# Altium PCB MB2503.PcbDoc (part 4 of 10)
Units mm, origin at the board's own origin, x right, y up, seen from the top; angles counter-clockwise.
Board outline 127 x 97 mm, 6 copper layers (Top Layer, Signal Layer 1, Signal Layer 2, Signal Layer 3, Signal Layer 4, Bottom Layer), stack 1.557 mm thick; 572 components, 468 nets, 2377 pads, 1704 vias.
Unrouted connection lines stored in the file: 3.
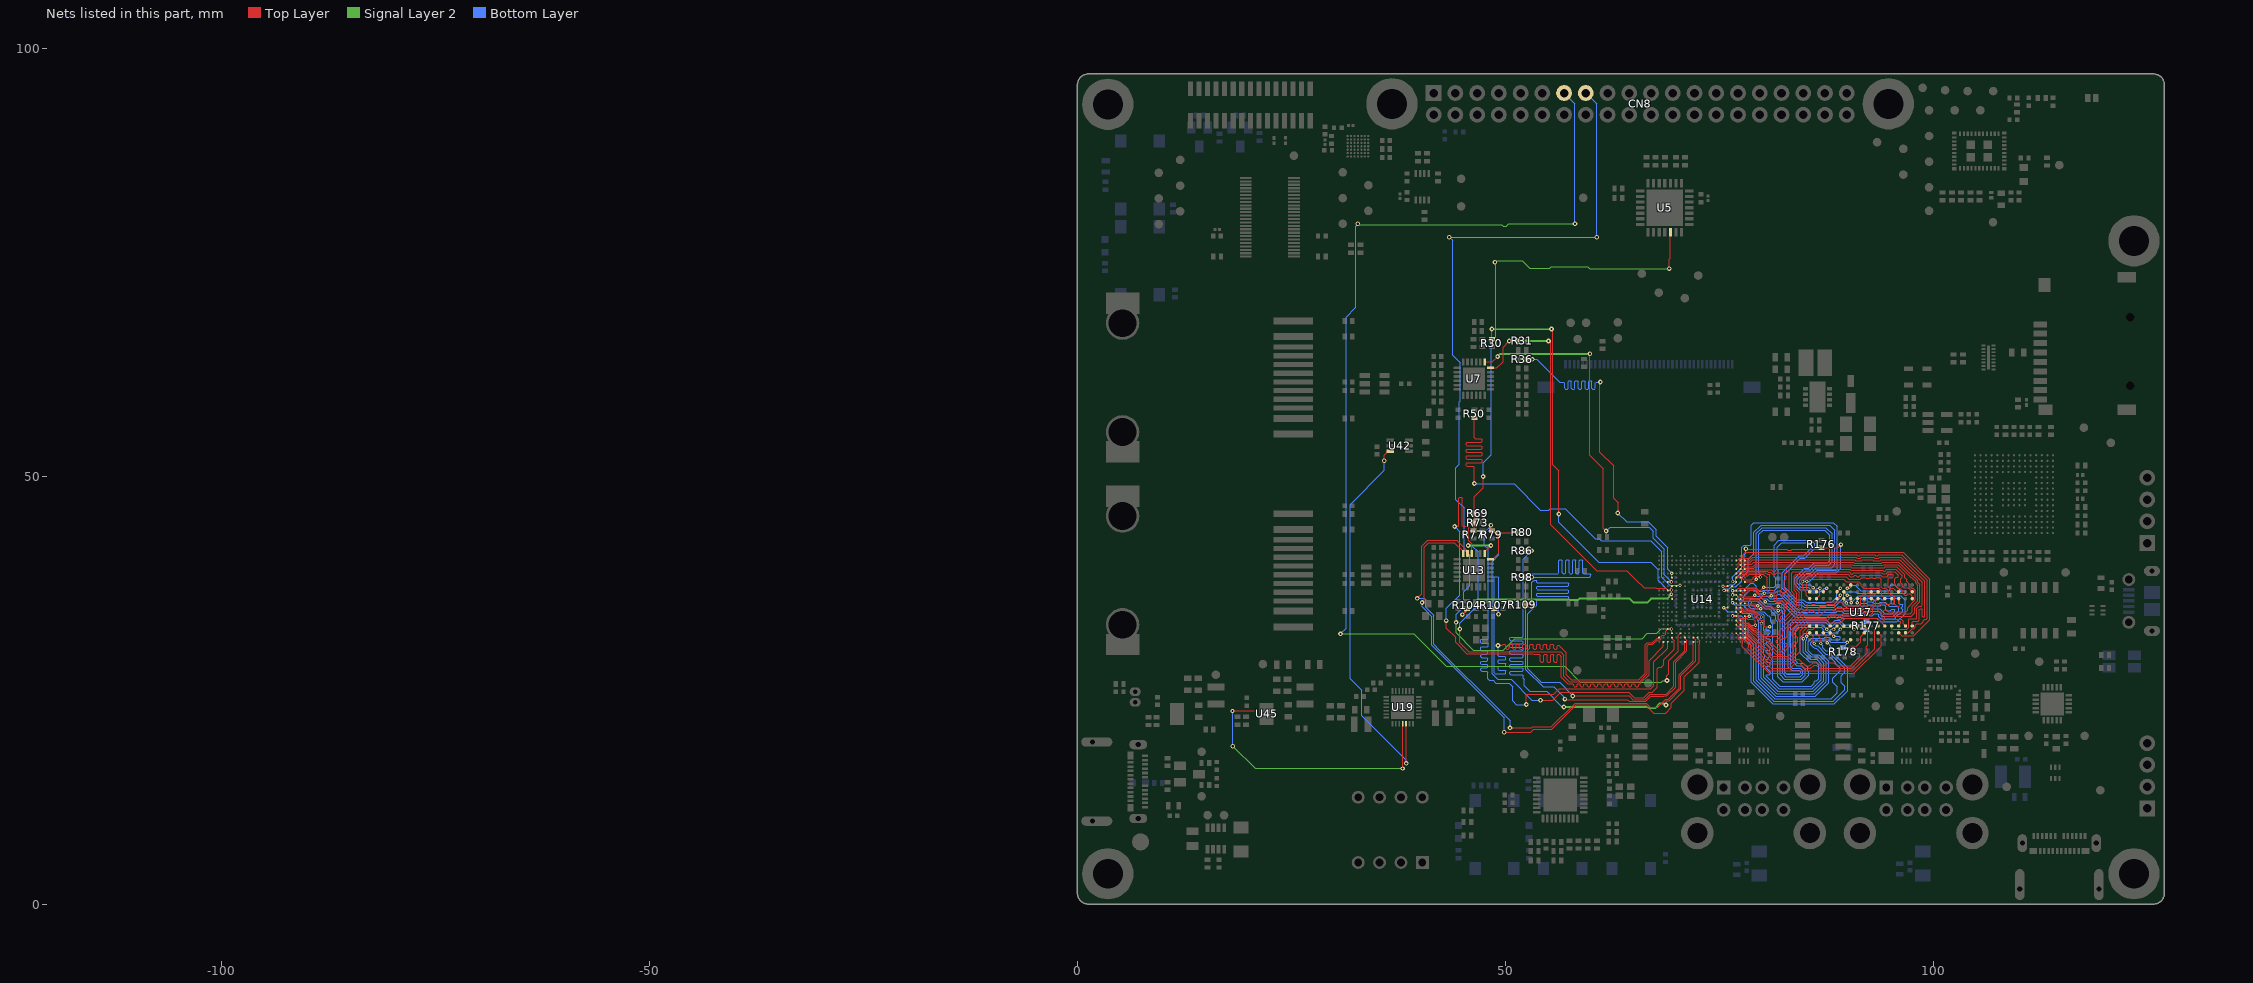
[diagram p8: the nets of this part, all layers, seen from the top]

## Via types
v1: diameter 0.55, hole 0.25, Top Layer to Bottom Layer, 1335 vias
v2: diameter 0.4, hole 0.2, Top Layer to Bottom Layer, 262 vias
v3: diameter 0.5, hole 0.2, Top Layer to Bottom Layer, 51 vias
v4: diameter 0.26, hole 0.1, Top Layer to Signal Layer 1, tented both sides, 29 vias
v5: diameter 0.5, hole 0.25, Top Layer to Bottom Layer, 18 vias
v6: diameter 0.4, hole 0.2, Top Layer to Bottom Layer, tented both sides, 9 vias

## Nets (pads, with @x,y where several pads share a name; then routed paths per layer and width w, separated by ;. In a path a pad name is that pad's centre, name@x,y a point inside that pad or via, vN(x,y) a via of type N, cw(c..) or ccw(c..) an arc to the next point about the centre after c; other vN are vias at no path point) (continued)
DDR_A4: U14.R19 U17.P8 | length 30.6
  Top Layer w0.09: U17.P8@87.15,31.7 87.495,31.355 v2@87.495,30.675 ; v2@87.5,30.675 87.6,30.575 v2(87.6,30.525)
  Top Layer w0.1: v2(76.55,33.675) 76.563,33.663 76.962,33.663 U14.R19@76.975,33.65
  Bottom Layer w0.09: v2(76.55,33.675) 76.558,33.683 77.567,33.683 77.8,33.45 77.8,31.1 78.71,30.19 78.71,25.907 81.219,23.398 88.448,23.398 90,24.95 90,27.629 88.45,29.179 88.45,29.662 87.98,30.132 87.98,30.195 87.65,30.525 v2(87.6,30.525)
DDR_A5: U14.F20 U17.P2 | length 30.1
  Top Layer w0.075: U14.F20@77.47,38.145 77.479,38.136 77.635,38.136 77.871,37.9 78.31,37.9 78.33,37.88 78.768,37.88 78.974,38.086 78.974,38.174 79.123,38.323 79.618,38.323 79.716,38.225 v2(79.8,38.225)
  Top Layer w0.09: U17.P2@87.145,36.495 v2(87.55,36.9)
  Bottom Layer w0.09: v2(79.8,38.225) 79.8,38.515 79.615,38.7 79.615,43.19 80.125,43.7 87.3,43.7 87.905,43.095 87.905,40.13 87.665,39.89 86.092,39.89 85.447,39.245 84.962,39.245 83.8,38.083 83.8,37.373 84.423,36.75 85.277,36.75 85.641,36.386 86.316,36.386 86.41,36.48 86.818,36.48 87.238,36.9 v2(87.55,36.9)
DDR_A6: U14.R21 U17.R8 | length 29.7
  Top Layer w0.09: U14.R21@77.974,33.65 78.5,33.65 v2(78.5,33.625) ; U17.R8@86.35,31.7 86.675,31.375 86.675,31.178 86.775,31.078 86.775,30.801 86.844,30.732 86.844,30.456 v2(86.85,30.45)
  Bottom Layer w0.09: v2(78.5,33.625) 78.181,33.625 78.09,33.534 78.09,31.22 79,30.31 79,26.027 81.339,23.688 88.328,23.688 89.66,25.02 89.66,25.465 89.25,25.875 89.25,26.665 89.66,27.075 89.66,27.559 88.16,29.059 88.16,29.39 87.95,29.6 87.447,29.6 87.074,29.973 87.074,30.173 86.85,30.397 v2(86.85,30.45)
DDR_A7: U14.J17 U17.R2 | length 31.4
  Top Layer w0.09: v2@75.47,36.645 U14.J17@75.97,36.645 ; v2@75.525,36.65 v2(75.55,36.65) U14.J17@75.975,36.65 ; v2(85.95,36.975) 86.35,36.575 U17.R2@86.35,36.5
  Bottom Layer w0.09: v2(75.55,36.65) 75.774,36.875 76.187,36.875 76.382,37.07 76.929,37.07 77.61,37.751 77.61,38.11 78.4,38.9 78.4,40.287 79.035,40.922 79.035,43.43 79.885,44.28 87.895,44.28 88.485,43.69 88.485,39.635 88.16,39.31 86.333,39.31 85.688,38.665 85.202,38.665 84.38,37.843 84.38,37.557 84.607,37.33 85.595,37.33 v2(85.95,36.975)
DDR_A8: U14.P19 U17.T8 | length 31
  Top Layer w0.075: U14.P19@76.975,34.15 77.225,33.9 77.225,33.5 77.325,33.4 78.175,33.4 78.295,33.28 78.667,33.28 78.682,33.295 78.968,33.295 79.17,33.093 79.17,32.655 v2(79.225,32.6)
  Top Layer w0.09: U17.T8@85.55,31.7 85.975,31.275 85.975,30.55 v2(86.075,30.45)
  Bottom Layer w0.09: v2(79.225,32.6) 78.55,32.6 78.38,32.43 78.38,31.34 79.29,30.43 79.29,26.147 81.459,23.979 83.35,23.979 ; 83.35,23.978 87.225,23.978 ; v2(86.075,30.45) 86.075,30.4 86.05,30.375 86.26,30.165 86.472,30.165 87.437,29.2 87.609,29.2 88.525,28.284 88.525,28.15 89.125,27.55 89.125,27.25 88.25,26.375 88.25,25.95 88.8,25.4 88.8,24.675 88.103,23.978 87.246,23.978
DDR_A9: U14.G21 U17.R3 | length 29.5
  Top Layer w0.075: U14.G21@77.975,37.65 77.998,37.673 79.023,37.673 v2(79.325,37.975)
  Top Layer w0.09: U17.R3@86.345,35.695 86.75,36.1 v2(86.75,36.9)
  Bottom Layer w0.09: v2(79.325,37.975) 79.325,43.31 80.005,43.99 87.46,43.99 88.195,43.255 88.195,40.01 87.785,39.6 86.212,39.6 85.567,38.955 85.082,38.955 84.09,37.963 84.09,37.465 84.515,37.04 85.397,37.04 85.807,36.63 86.15,36.63 86.42,36.9 v2(86.75,36.9)
DDR_A10: U14.L18 U17.L7 | length 31.5
  Top Layer w0.09: v2(89.145,32.095) U17.L7@89.545,32.495
  Top Layer w0.1: U14.L18@76.475,35.65 76.475,35.356 76.55,35.281 v2(76.55,35.2)
  Bottom Layer w0.09: v2(76.55,35.2) 76.775,34.975 77.725,34.975 78.435,34.265 78.885,34.265 78.995,34.155 80.218,34.155 80.678,33.695 80.768,33.695 80.995,33.468 80.995,32.98 81.245,32.73 81.245,31.52 81.098,31.373 81.098,31.277 81.245,31.13 81.245,30.62 81.035,30.41 81.035,30.335 81.245,30.125 81.245,28.825 81.15,28.73 81.15,28.575 81.245,28.48 81.245,26.259 82.075,25.429 85.713,25.429 86.105,25.82 86.105,26.005 86.208,26.108 86.392,26.108 86.64,26.355 86.64,27.907 86.237,28.31 85.497,28.31 84.48,29.327 84.48,31.143 84.982,31.645 85.38,31.645 85.575,31.45 88,31.45 88.287,31.737 88.787,31.737 v2(89.145,32.095)
DDR_A11: U14.N17 U17.R7 | length 31.2
  Top Layer w0.09: v2(75.525,34.625) 75.538,34.638 75.962,34.638 U14.N17@75.975,34.65 ; v2(85.225,31.3) 85.205,31.32 85.205,31.843 85.466,32.104 85.974,32.104 86.35,32.48 U17.R7@86.35,32.5
  Bottom Layer w0.09: v2(75.525,34.625) 75.978,34.173 76.873,34.173 76.951,34.251 76.951,34.551 77.05,34.65 77.525,34.65 77.625,34.55 77.625,34.05 77.7,33.975 78.675,33.975 78.85,33.8 78.85,33.55 78.925,33.475 79.225,33.475 79.65,33.9 80.063,33.9 80.27,33.693 80.27,32.47 80.171,32.371 80.171,31.93 80.25,31.851 80.25,31.4 80.171,31.321 80.171,30.319 80.257,30.232 80.257,29.793 80.171,29.706 80.171,29.179 80.331,29.019 80.331,28.924 80.171,28.764 80.171,26.496 81.819,24.849 85.953,24.849 87.22,26.115 87.22,28.148 86.478,28.89 85.737,28.89 85.1,29.527 85.1,30.783 85.225,30.908 v2(85.225,31.3)
DDR_A12: U14.M19 U17.N7 | length 31.3
  Top Layer w0.075: U14.M19@76.98,35.145 77.225,34.9 78.962,34.9 79.332,34.53 79.795,34.53 v2(79.825,34.5)
  Top Layer w0.1: v2(87.55,32.1) U17.N7@87.95,32.5
  Bottom Layer w0.09: v2(79.825,34.5) 79.065,34.5 79.01,34.555 78.685,34.555 78.41,34.83 78.41,35.345 78.745,35.68 79.532,35.68 80.244,34.969 ; 80.249,34.974 80.413,34.81 80.963,34.81 81.335,34.438 81.335,34.358 81.865,33.828 81.865,33.34 82.115,33.09 82.115,26.776 82.593,26.299 84.587,26.299 85.04,26.751 85.04,27.399 84.574,27.865 84.055,27.865 83.61,28.31 83.61,32.09 84.185,32.665 87.008,32.665 87.55,32.123 v2(87.55,32.1)
DDR_A13: U14.G19 U17.T3 | length 30.7
  Top Layer w0.09: v2(84.725,37.7) 84.725,36.897 85.175,36.447 85.175,36.065 U17.T3@85.545,35.695
  Top Layer w0.1: v2(76.55,37.7) 76.925,37.7 U14.G19@76.975,37.65
  Bottom Layer w0.09: v2(76.55,37.7) 76.55,38.237 77.625,39.312 77.625,41.675 77.896,41.946 78.639,41.946 78.745,42.052 78.745,44.295 79.02,44.57 88.33,44.57 88.775,44.125 88.775,39.125 88.67,39.02 86.453,39.02 85.808,38.375 85.4,38.375 v2(84.725,37.7)
DDR_A14: U14.N19 U17.T7 | length 30.9
  Top Layer w0.075: U14.N19@76.975,34.65 77.225,34.4 77.573,34.4 77.642,34.331 77.693,34.331 77.789,34.234 78.147,34.234 78.267,34.355 78.786,34.355 79.425,33.716 79.425,33.559 79.839,33.145 80.18,33.145 80.27,33.055 80.27,32.48 80.325,32.425 v2(80.9,32.425)
  Top Layer w0.09: v2(84.825,31) 84.825,31.901 85.424,32.5 U17.T7@85.55,32.5
  Bottom Layer w0.09: v2(80.9,32.425) 80.635,32.425 80.461,32.251 80.461,32.05 80.536,31.975 80.825,31.975 80.955,31.845 80.955,31.695 80.461,31.201 80.461,31.089 80.55,31 80.85,31 80.955,30.895 80.955,30.788 80.848,30.68 80.58,30.68 80.461,30.561 80.461,30.439 80.955,29.945 80.955,29.755 80.875,29.675 80.55,29.675 80.461,29.586 80.461,29.414 80.55,29.325 80.875,29.325 80.955,29.245 80.955,28.995 80.461,28.501 80.461,28.364 80.575,28.25 80.875,28.25 80.955,28.17 80.955,27.88 80.875,27.8 80.536,27.8 80.461,27.725 80.461,27.589 80.95,27.1 80.95,26.925 80.85,26.825 80.525,26.825 80.461,26.761 80.461,26.632 81.955,25.139 85.833,25.139 86.93,26.235 86.93,28.028 86.358,28.6 85.617,28.6 84.81,29.407 84.81,30.985 v2(84.825,31)
DDR_A15: U14.M21 U17.M7 | length 29.8
  Top Layer w0.075: U14.M21@77.974,35.15 78,35.125 79.225,35.125 v2(79.475,34.875)
  Top Layer w0.09: v2(88.35,32.1) U17.M7@88.75,32.5
  Bottom Layer w0.09: v2(79.475,34.875) 78.775,34.875 78.7,34.95 78.7,35.225 78.85,35.375 79.438,35.375 80.293,34.52 80.843,34.52 81.045,34.318 81.045,34.238 81.575,33.708 81.575,33.22 81.825,32.97 81.825,26.58 82.396,26.009 84.707,26.009 85.457,26.759 85.457,27.132 85.33,27.26 85.33,27.656 84.831,28.155 84.175,28.155 83.9,28.43 83.9,31.97 84.305,32.375 86.888,32.375 87.125,32.138 87.125,31.875 87.26,31.74 87.69,31.74 88.05,32.1 v2(88.35,32.1)
DDR_BA0: U14.J19 U17.M2 | length 30.9
  Top Layer w0.075: U14.J19@76.97,36.645 77.175,36.85 77.222,36.897 78.287,36.897 78.29,36.9 78.293,36.9 78.386,36.993 79.059,36.993 79.164,36.889 79.324,36.889 79.532,36.68 79.818,36.68 80.163,37.025 v2(80.175,37.025)
  Top Layer w0.09: U17.M2@88.745,36.495 v2@89.145,36.895
  Bottom Layer w0.09: v2(80.175,37.025) 81.087,37.025 81.107,37.005 81.393,37.005 81.595,37.207 81.595,38.018 81.388,38.225 81.388,41.96 81.928,42.5 85.75,42.5 86.125,42.125 86.125,41.563 84.967,40.405 84.474,40.405 82.64,38.57 82.64,37.006 84.056,35.59 84.796,35.59 85.141,35.245 88.124,35.245 88.735,35.855 88.735,36.406 89.15,36.821 v2@89.15,36.982
  other v2: 89.15,36.9
DDR_BA1: U14.P20 U17.N8 | length 30.3
  Top Layer w0.075: U14.P20@77.475,34.15 77.635,34.15 77.719,34.065 78.217,34.065 78.325,34.174 78.719,34.174 79.113,33.779 79.113,33.63 79.51,33.234 79.51,33.05 79.76,32.8 v2(79.925,32.8)
  Top Layer w0.09: U17.N8@87.95,31.7 v2(88.35,31.3)
  Bottom Layer w0.09: v2(79.925,32.8) 79.925,32.55 79.87,32.495 79.87,26.387 81.699,24.559 86.073,24.559 87.51,25.995 87.51,28.268 86.623,29.155 85.882,29.155 85.405,29.632 85.405,30.678 85.812,31.085 87.25,31.085 87.325,31.16 87.863,31.16 88.113,30.91 89.035,30.91 89.125,31 89.125,31.175 89,31.3 v2(88.35,31.3)
DDR_BA2: U14.H18 U17.M3 | length 31.6
  Top Layer w0.09: U14.H18@76.475,37.15 76.475,36.784 76.55,36.709 v2(76.55,36.625) ; U17.M3@88.745,35.695 v2@89.125,36.075
  Bottom Layer w0.09: v2(76.55,36.625) 77.789,36.625 78.653,37.489 78.986,37.489 79.312,37.163 79.312,36.888 79.65,36.55 80.007,36.55 80.137,36.68 81.478,36.68 81.905,37.107 81.905,38.923 81.775,39.053 81.775,41.674 82.311,42.21 85.54,42.21 85.8,41.95 85.8,41.648 84.847,40.695 84.354,40.695 82.35,38.69 82.35,36.914 83.964,35.3 84.676,35.3 85.026,34.95 88.292,34.95 89.15,35.808 v2(89.15,36.1) v2@89.172,36.122
DDR_CASN: U14.L19 U17.K3 | length 30.4
  Top Layer w0.075: U14.L19@76.974,35.65 77.15,35.825 77.221,35.896 77.631,35.896 77.793,35.734 79.966,35.734 v2(80.375,35.325)
  Top Layer w0.09: U17.K3@90.35,35.7 90.387,35.662 90.387,35.237 v2(90.425,35.2)
  Bottom Layer w0.09: v2(80.375,35.325) 80.387,35.325 80.612,35.1 81.537,35.1 81.582,35.145 82.23,35.145 83.875,33.5 89.195,33.5 89.293,33.402 93.413,33.402 93.841,32.974 95.74,32.974 96.7,33.934 96.7,35.513 96.203,36.01 91.235,36.01 v2(90.425,35.2)
DDR_CKE: R178.2 U14.N20 U17.K9 | length 31.7
  Top Layer w0.075: U14.N20@77.47,34.645 77.627,34.645 77.869,34.403 78.077,34.403 78.212,34.538 78.843,34.538 79.396,33.985 79.49,33.985 v2(79.925,33.55)
  Top Layer w0.09: v2(89.95,30.575) 90.025,30.575 U17.K9@90.35,30.9
  Bottom Layer w0.09: v2(79.925,33.55) 79.925,33.525 79.58,33.18 79.58,26.267 81.579,24.269 84.3,24.269 86.193,24.268 87.8,25.875 87.8,28.388 86.318,29.87 86.145,29.87 85.915,30.1 85.912,30.1 85.705,30.307 85.705,30.568 85.932,30.795 87.37,30.795 87.445,30.87 87.743,30.87 87.993,30.62 v2@89.905,30.62 ; R178.2@89.475,29.975 89.564,29.975 89.774,30.185 89.774,30.292 89.891,30.408 89.891,30.516 v2(89.95,30.575) v2@89.95,30.62
DDR_CLK_N: R177.2 U14.L20 U17.K7 | length 32.9
  Top Layer w0.075: U14.L20@77.496,35.64 77.526,35.64 77.601,35.565 79.611,35.565 80.335,34.841 81.086,34.841 81.269,34.658 81.758,34.658 v2(81.9,34.8)
  Top Layer w0.09: U17.K7@90.35,32.5 90.35,32.525 v2(90.725,32.9)
  Bottom Layer w0.09: v2(81.9,34.8) 81.973,34.8 82.111,34.661 82.339,34.661 82.665,34.335 82.665,27.066 82.883,26.849 84.359,26.849 84.49,26.979 84.49,27.171 84.346,27.315 83.437,27.315 83.06,27.692 83.06,32.924 83.356,33.22 83.36,33.22 ; 83.36,33.21 87.494,33.21 87.929,32.775 88.15,32.775 88.55,33.175 89.035,33.175 89.585,32.625 90.45,32.625 v2(90.725,32.9) 91,32.625 91.725,32.625 92.075,32.975 R177.2@92.175,32.975
DDR_CLK_P: R177.1 U14.M20 U17.J7 | length 33
  Top Layer w0.075: U14.M20@77.475,35.15 77.721,35.396 78.118,35.396 78.144,35.37 79.53,35.37 80.254,34.646 81.005,34.646 81.188,34.463 81.737,34.463 v2(81.9,34.3)
  Top Layer w0.09: v2(90.725,32.1) 90.75,32.1 U17.J7@91.15,32.5
  Bottom Layer w0.09: v2(81.9,34.3) 81.975,34.3 82.076,34.401 82.231,34.401 82.405,34.227 82.405,26.959 82.775,26.589 84.467,26.589 84.75,26.871 84.75,27.279 84.454,27.575 83.544,27.575 83.32,27.799 83.32,32.816 83.453,32.95 87.38,32.95 87.386,32.95 87.821,32.515 88.258,32.515 88.658,32.915 88.927,32.915 89.477,32.365 90.46,32.365 v2(90.725,32.1) ; R177.1@92.175,32.075 92.017,32.075 91.727,32.365 91.015,32.365 v2@90.75,32.1 ; v2(90.725,32.1) v2@90.75,32.1 ; v2(90.725,32.1) v2@90.75,32.1
DDR_CSN: U14.J20 U17.L2 | length 30.3
  Top Layer w0.075: U14.J20@77.47,36.645 77.715,36.4 78.274,36.4 78.527,36.653 78.918,36.653 79.023,36.549 79.183,36.549 79.706,36.026 ; 79.706,36.02 79.815,36.02 79.855,35.98 80.413,35.98 80.458,36.025 v2(81.075,36.025)
  Top Layer w0.09: U17.L2@89.545,36.495 v2(89.945,36.095)
  Bottom Layer w0.09: v2(81.075,36.025) 81.645,36.025 81.82,36.2 82.1,36.2 82.275,36.025 82.474,36.025 84.129,34.37 84.245,34.37 84.378,34.503 84.653,34.503 84.786,34.37 88.532,34.37 88.887,34.725 89.2,34.725 89.651,34.274 91.617,34.274 91.848,34.505 93.745,34.505 94.33,33.92 95.177,33.92 95.5,34.243 95.5,34.4 95.425,34.475 95.15,34.475 94.95,34.275 94.55,34.275 94.425,34.4 94.425,34.802 94.252,34.975 93.935,34.975 93.81,34.85 92.89,34.85 92.732,35.007 92.478,35.007 92.321,34.85 91.711,34.85 91.425,34.565 89.96,34.565 89.5,35.025 89.5,35.338 89.702,35.54 90.24,35.54 90.4,35.7 90.4,35.95 90.255,36.095 v2(89.945,36.095)
DDR_DQ0: U14.B21 U17.A7 | length 30.9
  Top Layer w0.09: U14.B21@77.97,40.145 78.52,40.145 78.89,40.515 81.275,40.515 90.977,40.515 91.073,40.42 91.505,40.42 91.6,40.515 93.043,40.515 93.138,40.42 93.625,40.42 93.72,40.515 96.222,40.515 99.015,37.721 99.015,33.64 98.94,33.565 98.753,33.565 98.7,33.617 98.7,34.484 98.647,34.536 98.465,34.536 98.375,34.446 98.375,33.219 98.215,33.06 97.635,33.06 97.539,32.964 97.539,32.501 U17.A7@97.545,32.495
DDR_DQ1: U14.B20 U17.B8 | length 31.4
  Top Layer w0.075: U14.B20@77.475,40.15 77.485,40.16 77.636,40.16 77.876,40.4 78.513,40.4
  Top Layer w0.09: 78.513,40.4 78.918,40.805 91.098,40.805 91.193,40.71 91.377,40.71 91.472,40.805 93.163,40.805 93.258,40.71 93.505,40.71 93.6,40.805 96.342,40.805 99.305,37.842 99.305,33.39 99.19,33.275 98.975,33.275 98.8,33.1 98.8,33 98.57,32.77 98.085,32.77 97.895,32.58 97.895,32.357 97.688,32.15 97.5,32.15 ; U17.B8@96.75,31.7 97.05,31.7 97.495,32.145
DDR_DQ2: U14.D19 U17.D7 | length 32.7
  Top Layer w0.075: U14.D19@76.97,39.145 77.221,39.396 77.221,39.856 77.265,39.9 78.555,39.9
  Top Layer w0.09: 78.555,39.9 78.88,40.225 81.275,40.225 90.829,40.225 90.924,40.13 91.625,40.13 91.72,40.225 92.923,40.225 93.018,40.13 93.775,40.13 93.87,40.225 96.101,40.225 98.725,37.601 98.725,34.9 98.652,34.826 98.345,34.826 98.085,34.566 98.085,33.404 98.032,33.351 97.217,33.351 97.14,33.274 97.14,32.323 96.917,32.1 95.254,32.1 95.15,32.204 U17.D7@95.15,32.5
DDR_DQ3: U14.E19 U17.A3 | length 32.6
  Top Layer w0.075: U14.E19@76.996,38.671 77.15,38.671 77.228,38.75 77.228,38.752 77.373,38.897 77.603,38.897 77.765,38.735 77.805,38.735 78.147,38.735 78.312,38.9 80.575,38.9
  Top Layer w0.09: 80.575,38.9 80.7,38.775 80.98,38.775 81.23,38.525 81.54,38.525 81.717,38.702 82.036,38.702 82.275,38.463 82.275,36.775 82.115,36.615 82.115,36.07 82.888,35.298 82.888,34.598 83.015,34.47 83.225,34.47 83.759,35.005 83.759,36.223 83.435,36.547 83.435,38.677 83.572,38.815 90.165,38.815 90.43,38.55 90.522,38.55 90.692,38.72 93.99,38.72 94.085,38.625 94.49,38.625 94.68,38.815 95.517,38.815 95.885,38.447 95.885,38.247 95.832,38.195 95.675,38.195 95.48,37.999 95.48,37.45 95.525,37.404 95.525,37.219 95.865,36.88 96.076,36.88 96.345,36.611 96.345,36.4 96.647,36.098 96.873,36.098 97.025,36.25 97.291,36.25 97.55,35.991 U17.A3@97.55,35.7
DDR_DQ4: U14.B19 U17.C8 | length 33.7
  Top Layer w0.075: U14.B19@76.975,40.15 76.985,40.16 77.136,40.16 77.373,40.397 77.589,40.397 77.725,40.532 77.725,40.773
  Top Layer w0.09: 77.725,40.773 78.047,41.095 79.4,41.095 96.462,41.095 99.595,37.962 99.595,33.254 97.694,31.354 96.296,31.354 U17.C8@95.95,31.7
DDR_DQ5: U14.D20 U17.A2 | length 32
  Top Layer w0.075: U14.D20@77.484,39.131 77.637,39.131 77.865,38.904 78.077,38.904 78.248,39.075 80.5,39.075 80.502,39.077 80.648,39.077 80.65,39.075 81.075,39.075
  Top Layer w0.09: 81.075,39.075 81.3,38.85 81.455,38.85 81.705,39.1 82.775,39.1 82.85,39.025 82.85,38.875 82.617,38.642 82.617,38.433 82.803,38.247 82.803,38.028 82.565,37.79 82.565,36.91 82.85,36.625 82.85,36.5 82.795,36.445 82.47,36.445 82.405,36.38 82.405,36.19 82.525,36.07 83.005,36.07 83.178,35.897 83.178,35.078 83.23,35.025 83.37,35.025 83.469,35.125 83.469,36.102 83.145,36.427 83.145,39.045 83.205,39.105 90.285,39.105 90.38,39.01 94.11,39.01 94.205,38.915 94.37,38.915 94.56,39.105 95.638,39.105 96.379,38.363 96.379,38.203 96.175,37.999 96.175,37.571 96.387,37.359 96.387,37.172 96.604,36.955 97.085,36.955 U17.A2@97.545,36.495
DDR_DQ6: U14.E20 U17.C2 | length 32
  Top Layer w0.075: U14.E20@77.492,38.623 77.637,38.623 77.695,38.566 77.875,38.566 ; 77.875,38.566 78.217,38.566 78.227,38.575 78.383,38.731 80.364,38.731 80.364,38.729 80.364,38.723
  Top Layer w0.09: 80.377,38.723 80.58,38.52 80.825,38.52 80.885,38.46 80.885,36.765 80.975,36.675 81.325,36.675 81.477,36.523 81.727,36.523 81.825,36.425 81.825,36.2 81.71,36.085 81.71,35.615 81.785,35.54 82.235,35.54 82.598,35.177 82.598,34.477 82.725,34.35 82.725,34.155 82.165,33.595 82.165,33.329 82.218,33.276 82.441,33.276 84.049,34.884 84.049,36.343 83.725,36.667 83.725,38.29 83.96,38.525 90.045,38.525 90.31,38.26 90.642,38.26 90.812,38.43 90.957,38.43 91.127,38.26 91.266,38.26 91.436,38.43 92.208,38.43 93.87,38.43 94.025,38.275 94.55,38.275 94.8,38.525 95.25,38.525 95.325,38.45 95.325,38.275 95.195,38.145 94.902,38.145 94.75,37.993 94.75,37.1 94.95,36.9 95.2,36.9 ; 95.2,36.9 95.325,36.9 95.685,36.54 95.91,36.54 U17.C2@95.95,36.5
DDR_DQ7: U14.F19 U17.C3 | length 32.8
  Top Layer w0.075: U14.F19@76.989,38.164 77.138,38.164 77.372,38.397 78.324,38.397 78.49,38.562 80.143,38.562 80.143,38.559 80.149,38.559 80.153,38.554
  Top Layer w0.09: 80.153,38.554 80.158,38.554 80.595,38.118 80.595,36.645 80.865,36.375 81.215,36.375 81.42,36.17 81.42,35.48 81.65,35.25 82.115,35.25 82.308,35.057 82.308,34.148 81.875,33.715 81.875,33.199 82.088,32.986 82.561,32.986 84.339,34.764 84.339,36.463 84.015,36.787 84.015,38.115 84.135,38.235 89.875,38.235 ; 89.9,38.21 90.14,37.97 91.475,37.97 91.645,38.14 92.088,38.14 92.171,38.056 92.518,38.056 92.602,38.14 92.888,38.14 92.953,38.075 93.266,38.075 93.331,38.14 93.75,38.14 93.947,37.943 93.947,37.028 94.075,36.9 94.45,36.9 94.745,36.605 94.745,36.4 95,36.145 95.215,36.145 95.525,35.835 95.525,35.046 95.771,34.8 96,34.8 96.1,34.9 96.1,35.08 95.95,35.23 U17.C3@95.95,35.7
DDR_DQ8: U14.T20 U17.E3 | length 24.3
  Top Layer w0.075: U14.T20@77.48,33.135 77.634,33.135 77.865,32.903 78.185,32.903 78.375,32.903 79.034,32.244 79.256,32.244
  Top Layer w0.09: 79.256,32.244 80.2,31.3 81.735,31.3 82.025,31.59 82.025,31.95 84.629,34.554 84.629,36.583 84.38,36.832 84.38,37.843 84.582,38.045 85.43,38.045 85.53,37.945 89.564,37.945 89.829,37.68 91.287,37.68 91.57,37.396 91.57,37.175 91.85,36.895 93.65,36.895 93.965,36.58 93.965,36.085 U17.E3@94.345,35.705
DDR_DQ9: U14.U20 U17.H3 | length 22.2
  Top Layer w0.075: U14.U20@77.47,32.645 77.643,32.645 77.723,32.565 78.235,32.565 79,31.8 79.15,31.8
  Top Layer w0.09: 79.15,31.8 80.088,30.863 80.338,30.863 81.69,29.51 82.22,29.51 82.95,30.24 82.95,30.375 82.85,30.475 82.325,30.475 82.175,30.625 82.175,30.825 82.413,31.063 82.688,31.063 82.95,31.325 82.95,32.04 84.88,33.97 85.295,33.97 85.675,34.35 85.875,34.35 86.255,33.97 86.55,33.97 86.7,34.12 86.7,34.675 86.81,34.785 87.435,34.785 87.687,35.037 88.373,35.037 88.5,34.91 88.5,34.625 88.575,34.55 89.592,34.55 91.599,34.55 91.945,34.896 U17.H3@91.945,35.695
DDR_DQ10: U14.T19 U17.G2 | length 22.9
  Top Layer w0.075: U14.T19@76.975,33.15 77.225,32.9 77.628,32.9 77.794,32.734 78.305,32.734 79.039,32 79.225,32
  Top Layer w0.09: 79.225,32 80.116,31.109 80.516,31.109 81.825,29.8 82.1,29.8 82.175,29.875 82.175,30.1 81.65,30.625 81.65,30.765 82.4,31.515 82.4,31.9 84.76,34.26 85.11,34.26 85.3,34.45 85.3,35.04 85.439,35.178 85.675,35.178 85.828,35.025 86.175,35.025 86.328,35.178 87.419,35.178 87.578,35.337 89.188,35.337 89.5,35.025 89.5,34.9 89.56,34.84 89.712,34.84 91.278,34.84 91.39,34.84 91.548,34.998 91.548,35.923 91.75,36.125 92.075,36.125 92.445,36.495 U17.G2@92.745,36.495
DDR_DQ11: U14.W20 U17.H8 | length 21.9
  Top Layer w0.075: U14.W20@77.48,31.635 77.634,31.635 77.872,31.396 78.079,31.396 78.75,30.725
  Top Layer w0.09: 78.75,30.725 78.75,30.675 78.95,30.475 78.95,30.045 80.895,28.1 83.424,28.1 83.932,28.608 84.297,28.608 85.075,27.83 85.555,27.83 85.95,28.225 86.455,28.225 86.85,27.83 87.28,27.83 87.675,28.225 88.355,28.225 88.75,27.83 90.339,27.83 91.425,28.916 91.425,29.168 91.268,29.325 90.5,29.325 90.375,29.45 90.375,29.967 90.483,30.075 90.925,30.075 91.5,30.65 91.5,31.25 U17.H8@91.95,31.7 U17.H8@91.925,31.7
DDR_DQ12: U14.W19 U17.F8 | length 22.5
  Top Layer w0.075: U14.W19@76.975,31.65 77.225,31.4 77.225,31.026 77.348,30.903 77.569,30.903 77.721,30.752 77.721,30.548 77.706,30.533
  Top Layer w0.09: 77.706,30.533 77.706,30.059 80.805,26.96 90.699,26.96 93.892,30.153 93.892,30.156 ; U17.F8@93.545,31.695 93.895,31.345 93.895,30.156
DDR_DQ13: U14.U19 U17.F2 | length 22.8
  Top Layer w0.075: U14.U19@76.975,32.65 77.229,32.396 78.154,32.396 78.95,31.6 79.075,31.6
  Top Layer w0.09: 79.075,31.6 80.218,30.457 80.332,30.457 81.57,29.22 82.34,29.22 83.24,30.12 83.24,31.9 85.02,33.68 86.727,33.68 87.523,34.475 88.1,34.475 88.315,34.26 89.675,34.26 91.325,34.26 91.719,34.26 92.32,34.861 92.32,35.795 92.65,36.125 93.175,36.125 U17.F2@93.545,36.495
DDR_DQ14: U14.Y21 U17.H7 | length 21.2
  Top Layer w0.075: U14.Y21@77.992,31.123 78.101,31.123 78.475,30.749 78.475,30.575 78.675,30.375
  Top Layer w0.09: 78.675,30.375 78.675,29.91 80.86,27.725 81.046,27.54 83.274,27.54 83.859,28.125 84.37,28.125 84.955,27.54 85.675,27.54 86.07,27.935 86.335,27.935 86.73,27.54 90.459,27.54 92.3,29.381 92.3,29.775 92.175,29.9 92.175,30.066 92.37,30.261 92.37,32.07 U17.H7@91.945,32.495
DDR_DQ15: U14.Y20 U17.F7 | length 21.7
  Top Layer w0.075: U14.Y20@77.474,31.15 77.625,31.15 77.872,30.903 78.072,30.903 78.288,30.688 78.288,30.492 78.4,30.379
  Top Layer w0.09: 78.414,30.365 78.414,30.085 78.4,30.071 78.4,29.775 80.45,27.725 80.925,27.25 90.579,27.25 93.15,29.821 93.15,32.1 U17.F7@93.55,32.5
DDR_DQM0: U14.D21 U17.D3 | length 31.2
  Top Layer w0.075: U14.D21@77.956,39.143 78.074,39.143 78.201,39.27 79.045,39.27 79.17,39.395
  Top Layer w0.09: 79.17,39.395 81.275,39.395 90.405,39.395 90.5,39.3 94.253,39.3 94.348,39.395 95.758,39.395 96.669,38.484 96.669,38.144 96.87,37.943 96.87,37.7 97.195,37.375 97.195,37.15 97.463,36.882 97.653,36.882 97.656,36.882 97.895,36.643 97.895,35.557 ; U17.D3@95.145,35.695 95.145,35.245 94.93,35.03 94.495,35.03 94.3,35.225 93.95,35.225 93.525,34.8 93.525,34.325 93.665,34.185 94.085,34.185 94.325,34.425 94.525,34.425 94.765,34.185 96.86,34.185 96.995,34.32 96.995,34.65 97.895,35.55 97.895,35.557 97.806,35.469
DDR_DQM1: U14.W21 U17.E7 | length 21.7
  Top Layer w0.075: U14.W21@78.013,31.645 78.016,31.645 78.096,31.565 78.159,31.565 79.295,30.43
  Top Layer w0.09: 79.295,30.43 79.295,30.111 81.015,28.39 83.304,28.39 84.45,29.536 84.45,31.936 85.363,32.85 89.175,32.85 89.73,33.405 93.096,33.405 93.111,33.42 93.439,33.42 94.35,32.508 U17.E7@94.35,32.5
DDR_DQS0_N: U14.C21 U17.B7 | length 32.3
  Top Layer w0.09: U14.C21@77.975,39.65 78.032,39.707 78.814,39.707 79.047,39.94 81.275,39.94 90.681,39.94 90.776,39.845 93.949,39.845 94.044,39.94 95.983,39.94 97.473,38.45 97.544,38.45 98.181,37.813 98.181,37.634 98.44,37.375 98.44,35.324 97.805,34.689 97.805,34.039 97.405,33.64 94.377,33.64 94.3,33.563 94.3,33.417 94.433,33.285 96.233,33.285 96.485,33.032 96.485,32.787 96.75,32.522 U17.B7@96.75,32.5
DDR_DQS0_P: U14.C20 U17.C7 | length 32.4
  Top Layer w0.075: U14.C20@77.496,39.65 77.746,39.4 78.093,39.4 78.139,39.447
  Top Layer w0.09: U14.C20@77.475,39.65 U14.C20@77.496,39.65 ; 78.139,39.447 78.922,39.447 79.155,39.68 81.275,39.68 90.573,39.68 90.668,39.585 94.056,39.585 94.151,39.68 95.876,39.68 97.366,38.19 97.436,38.19 97.665,37.961 97.921,37.705 97.921,37.526 98.18,37.267 98.18,35.432 97.545,34.797 97.545,34.147 97.298,33.9 94.269,33.9 94.04,33.671 94.04,33.31 94.325,33.025 96.125,33.025 96.225,32.925 96.225,32.8 95.95,32.525 U17.C7@95.95,32.5
DDR_DQS1_N: U14.V21 U17.G3 | length 22.3
  Top Layer w0.075: U14.V21@77.963,32.161 U14.V21@77.974,32.15 78.003,32.12 78.15,32.12 79.845,30.425
  Top Layer w0.09: 79.845,30.425 79.845,30.339 80.154,30.029 80.351,30.029 80.95,29.43 80.95,29.233 81.243,28.94 83.076,28.94 83.715,29.579 83.715,29.794 83.54,29.969 83.54,30.433 83.9,30.793 83.9,30.992 83.54,31.352 83.54,31.79 85.14,33.39 87.476,33.39 88.031,33.945 88.559,33.945 88.936,33.568 89.129,33.568 89.506,33.945 91.87,33.945 92,34.075 92.575,34.075 92.675,34.175 92.675,34.75 93.025,35.1 93.025,35.425 U17.G3@92.75,35.7
DDR_DQS1_P: U14.V20 U17.F3 | length 23.4
  Top Layer w0.075: U14.V20@77.474,32.15 77.725,31.9 78.094,31.9 79.585,30.409
  Top Layer w0.09: 79.585,30.409 79.585,30.231 80.046,29.769 80.243,29.769 80.69,29.322 80.69,29.126 81.136,28.68 83.184,28.68 83.975,29.471 83.975,29.902 83.8,30.077 83.8,30.325 84.16,30.685 84.16,31.1 83.8,31.46 83.8,31.682 85.247,33.13 87.584,33.13 88.139,33.685 88.451,33.685 88.828,33.308 89.237,33.308 89.614,33.685 91.978,33.685 92.108,33.815 92.683,33.815 92.935,34.067 92.935,34.642 93.285,34.992 93.285,35.435 U17.F3@93.55,35.7
DDR_ODT: U14.J21 U17.K1 | length 30.1
  Top Layer w0.075: U14.J21@77.975,36.65 78.283,36.65 78.456,36.823 78.988,36.823 79.093,36.719 79.253,36.719 79.627,36.345 v2@80.27,36.345
  Top Layer w0.09: v2@89.945,36.895 v2(89.95,36.9) U17.K1@90.345,37.295
  Bottom Layer w0.09: v2(80.27,36.325) 80.329,36.384 80.472,36.384 80.478,36.39 81.6,36.39 81.835,36.625 82.09,36.625 82.325,36.39 82.492,36.39 83.886,34.997 84.569,34.997 84.906,34.66 88.412,34.66 89.558,35.806 89.558,36.275 89.808,36.525 90.9,36.525 91.125,36.3 96.725,36.3 96.8,36.375 96.8,36.525 96.725,36.6 96.206,36.6 95.483,37.323 95.115,37.323 94.964,37.172 94.964,36.729 94.835,36.6 91.55,36.6 90.905,37.245 90.607,37.245 90.262,36.9 v2(89.95,36.9)
DDR_RASN: U14.K20 U17.J3 | length 30.7
  Top Layer w0.075: U14.K20@77.47,36.145 77.481,36.134 77.633,36.134 77.861,35.905 77.87,35.905 77.872,35.903 78.076,35.903 78.078,35.905 78.084,35.905 78.119,35.941 78.928,35.941 79.087,36.1 v2(79.125,36.1)
  Top Layer w0.09: v2@91.145,35.195 U17.J3@91.145,35.695
  Bottom Layer w0.09: v2(79.125,36.1) 79.184,36.041 79.339,36.041 79.41,35.97 79.727,35.97 80.007,35.69 80.512,35.69 80.812,35.39 81.417,35.39 81.462,35.435 82.315,35.435 83.96,33.79 89.315,33.79 89.411,33.694 91.857,33.694 92.089,33.925 92.35,33.925 92.583,33.692 92.85,33.692 93.083,33.925 93.505,33.925 93.635,33.795 93.635,33.59 93.885,33.34 95.505,33.34 95.632,33.468 95.632,33.555 95.932,33.855 96.02,33.855 96.41,34.245 96.41,34.39 96.25,34.55 96.25,34.625 96.41,34.785 96.41,34.97 96.35,35.03 96.07,35.03 96,35.1 96,35.65 95.93,35.72 95.545,35.72 95.462,35.637 95.462,35.237 95.35,35.125 95.15,35.125 95.095,35.18 95.095,35.663 95.038,35.72 94.37,35.72 94.225,35.575 93.97,35.575 93.825,35.72 93.436,35.72 93.352,35.636 93.352,35.485 93.297,35.43 93.13,35.43 92.84,35.72 92.225,35.72 92.15,35.645 92.15,35.5 92.08,35.43 91.82,35.43 91.53,35.72 91.355,35.72 91.125,35.49 v2(91.125,35.2)
DDR_RESETN: R176.2 U14.H17 U17.T2 | length 26.9
  Top Layer w0.09: v2(75.425,37.15) U14.H17@75.975,37.15 ; v1(78.1,41.525) 78.146,41.479 82.901,41.479 83.01,41.37 83.385,41.37 83.494,41.479 86.925,41.479 R176.2@86.971,41.525 ; v2(85.225,37.7) 85.205,37.68 85.205,36.835 U17.T2@85.545,36.495
  Top Layer w0.1: R176.2@86.925,41.625 88.825,41.625 v1(89.2,42)
  Bottom Layer w0.09: v2(75.425,37.15) 76.01,37.15 76.19,37.33 76.668,37.33 76.895,37.557 76.895,38.062 77.915,39.082 77.915,40.825 78.1,41.01 v1(78.1,41.525)
  Bottom Layer w0.1: v2(85.225,37.7) 85.225,37.694 85.178,37.647 85.497,37.647 85.59,37.74 85.59,37.745 86.195,38.35 86.2,38.35 86.575,38.725 88.657,38.725 89.2,39.268 v1(89.2,42)
DDR_WEN: U14.K19 U17.L3 | length 30.9
  Top Layer w0.09: v2@76.563,36.145 76.57,36.145 U14.K19@76.97,36.145 ; U17.L3@89.55,35.7 89.55,35.69 89.798,35.442 89.798,35.242 v2(89.845,35.195)
  Top Layer w0.1: v2(76.55,36.125) v2@76.57,36.145 ; U14.K19@76.97,36.145 U14.K19@76.975,36.15
  Bottom Layer w0.09: v2(76.55,36.125) 76.95,36.125 77.2,35.875 77.2,35.6 77.375,35.425 77.723,35.425 77.875,35.577 77.875,35.988 78.537,36.65 79.14,36.65 79.53,36.26 79.847,36.26 80.127,35.98 80.632,35.98 80.932,35.68 81.297,35.68 81.342,35.725 82.399,35.725 84.045,34.08 88.652,34.08 88.799,34.226 89.288,34.226 89.531,33.984 91.737,33.984 91.968,34.215 93.625,34.215 93.925,33.915 93.925,33.71 94.005,33.63 95.297,33.63 95.96,34.293 95.96,34.6 95.77,34.79 94.847,34.79 94.372,35.265 93.815,35.265 93.69,35.14 93.01,35.14 92.825,35.325 92.385,35.325 92.201,35.14 91.59,35.14 91.305,34.855 90.12,34.855 89.845,35.13 v2(89.845,35.195)
DFSDM1_CKOUT: CN8.13 U14.W6 | length 137
  Top Layer w0.075: 69.1,27.725 69.1,28.419 70.228,29.547 70.228,31.403 U14.W6@70.475,31.65
  Top Layer w0.1: v1(68.874,26.126) 68.874,26.674 69.1,26.9 69.1,27.725
  Signal Layer 2 w0.09: v1(32.752,79.504) 32.896,79.359 49.578,79.359 49.728,79.209 50.076,79.209 50.368,79.5 v1(58.125,79.5)
  Signal Layer 2 w0.1: v1(30.725,31.575) 39.289,31.575 43.089,27.775 56.917,27.775 58.742,25.95 68.201,25.95 68.376,26.125 v1@68.95,26.125
  Bottom Layer w0.09: CN8.13@56.86,94.77 58.125,93.505 v1(58.125,79.5)
  Bottom Layer w0.1: v1(30.725,31.575) 31.4,32.25 31.4,68.6 32.525,69.725 32.525,79.225 32.752,79.452 v1(32.752,79.504)
DFSDM1_DATIN3: CN8.15 U14.W4 | length 110.3
  Top Layer w0.1: v2@69.45,32.1 69.463,32.088 69.463,31.662 U14.W4@69.475,31.65
  Signal Layer 2 w0.09: 65.175,31.024 65.974,31.024 66.575,31.625 67.7,31.625 68.225,32.15 v2(69.4,32.15)
  Signal Layer 2 w0.1: v1(43.45,77.925) v1(60.675,77.925) ; v1(44.25,32.925) 44.25,31.7 46.275,29.675 49.775,29.675 51.124,31.024 65.175,31.024
  Bottom Layer w0.1: v1(43.45,77.925) 43.825,77.55 43.825,64.134 44.7,63.259 44.7,58.783 44.625,58.708 44.625,51.4 44.225,51 44.225,47.267 45.175,46.317 45.175,41.425 45.825,40.775 45.825,37.2 45.15,36.525 45.15,34.775 44.25,33.875 v1(44.25,32.925) ; CN8.15@59.4,94.77 60.675,93.495 v1(60.675,77.925)
EN1: U19.4 U45.2 | length 32.8
  Top Layer w0.1: v5(18.125,22.575) 20.6,22.575 U45.2@20.625,22.55 ; v5(38,15.85) U19.4@38,21.1
  Signal Layer 2 w0.1: v5(18.15,18.45) 20.75,15.85 v5(38,15.85)
  Bottom Layer w0.1: v5@18.125,18.45 18.137,18.463 18.137,22.562 v5(18.125,22.575)
EN2: U19.5 U42.3 | length 46
  Top Layer w0.1: v1(35.85,51.8) 35.85,52.45 36.3,52.9 U42.3@36.55,52.9 ; U19.5@38.4,21.125 38.413,21.112 38.413,16.462 v1(38.425,16.45)
  Bottom Layer w0.1: v1(35.85,51.8) 35.85,50.675 31.85,46.675 31.85,26.35 33.2,25 33.2,22.025 38.409,16.816 38.409,16.466 v1(38.425,16.45)
ETH1_CLK: R107.1 U14.Y1 | length 58.7
  Top Layer w0.075: 66.35,27.725 66.35,30.3 66.575,30.525 67.167,30.525 67.736,31.094 67.877,31.094 67.915,31.133 U14.Y1@67.915,31.15
  Top Layer w0.1: R107.1@48.725,34.5 48.775,34.5 49.2,34.075 v1(49.2,33.875) ; v1(49.15,30.225) 49.25,30.225 49.625,30.225 49.65,30.25 49.75,30.35 49.95,30.35 50.05,30.25 50.05,30.225 50.05,29.875 50.15,29.775 50.35,29.775 50.45,29.875 50.45,30.225 50.45,30.25 50.55,30.35 50.75,30.35 50.85,30.25 50.85,30.225 50.85,29.875 50.95,29.775 51.15,29.775 51.25,29.875 51.25,30.225 51.25,30.25 51.35,30.35 51.55,30.35 51.65,30.25 51.65,30.225 51.65,29.875 51.75,29.775 51.95,29.775 52.05,29.875 52.05,30.225 52.05,30.25 52.15,30.35 52.35,30.35 52.45,30.25 52.45,30.225 52.45,29.875 52.55,29.775 52.75,29.775 52.85,29.875 52.85,30.225 52.85,30.25 52.95,30.35 53.15,30.35 53.25,30.25 53.25,30.225 53.25,29.875 53.35,29.775 53.55,29.775 53.65,29.875 53.65,30.225 53.65,30.25 53.75,30.35 53.95,30.35 54.05,30.25 54.05,30.225 54.05,29.875 54.15,29.775 54.35,29.775 54.45,29.875 54.45,30.225 54.45,30.25 54.55,30.35 54.75,30.35 54.85,30.25 54.85,30.225 54.85,29.875 54.95,29.775 55.15,29.775 55.25,29.875 55.25,30.225 55.25,30.25 55.35,30.35 55.55,30.35 55.65,30.25 55.65,30.225 55.65,29.875 55.75,29.775 55.95,29.775 56.05,29.875 56.05,30.125 56.15,30.225 56.25,30.225 57.125,29.35 57.125,26.775 57.675,26.225 65.575,26.225 66.35,27 66.35,27.725
  Bottom Layer w0.1: v1(49.15,30.225) 49.15,29.05 49.225,28.975 49.95,28.975 50.025,28.9 50.025,28.634 49.966,28.575 49.225,28.575 49.15,28.5 49.15,28.225 49.225,28.15 49.966,28.15 50.025,28.091 50.025,27.834 49.966,27.775 49.225,27.775 49.15,27.7 49.15,27.425 49.225,27.35 49.966,27.35 50.025,27.291 50.025,26.984 49.966,26.925 48.775,26.925 48.675,27.025 48.675,38.191 48.734,38.25 49.1,38.25 49.2,38.15 v1(49.2,33.875)
ETH1_CRS_DV: R86.1 U14.Y9 | length 61.9
  Top Layer w0.075: 71.533,27.725 72.225,28.417 72.225,30.9 U14.Y9@71.975,31.15
  Top Layer w0.1: R86.1@52.425,41.275 v1(53.05,41.275) ; v1(68.775,23.275) 68.775,23.69 68.835,23.75 69.131,23.75 70.52,25.139 70.52,26.712 71.533,27.725
  Signal Layer 2 w0.219: v1(56.835,23.035) 56.85,23.05 66.591,23.05 66.741,22.9 67.5,22.9 68.05,23.45 68.51,23.45 68.685,23.275 v1(68.775,23.275)
  Bottom Layer w0.1: v1(53.05,41.275) 52.1,40.325 52.1,31.5 52.1,31.3 52,31.2 50.625,31.2 50.525,31.1 50.525,30.9 50.625,30.8 52,30.8 52.1,30.7 52.1,30.5 52,30.4 50.625,30.4 50.525,30.3 50.525,30.1 50.625,30 52,30 52.1,29.9 52.1,29.7 52,29.6 50.625,29.6 50.525,29.5 50.525,29.3 50.625,29.2 52,29.2 52.1,29.1 52.1,28.9 52,28.8 50.625,28.8 50.525,28.7 50.525,28.5 50.625,28.4 52,28.4 52.1,28.3 52.1,28.1 52,28 50.625,28 50.525,27.9 50.525,27.7 50.625,27.6 52,27.6 52.1,27.5 52.1,27.3 52,27.2 50.625,27.2 50.525,27.1 50.525,26.9 50.625,26.8 52,26.8 52.1,26.7 52.1,26.6 52.1,26.4 52.225,26.275 52.225,25.5 52.875,24.85 54.825,24.85 56.554,23.121 56.749,23.121 v1(56.835,23.035)
ETH1_MDC: U13.13 U14.V3 | length 49.3
  Top Layer w0.075: 66.575,27.725 66.575,30.2 66.725,30.35 67.231,30.35 67.781,30.9 68.125,30.9 68.225,31 68.225,31.275 68.35,31.4 68.573,31.4 68.725,31.552 68.725,31.9 U14.V3@68.975,32.15
  Top Layer w0.1: v1(44.678,32.153) 44.675,32.15 44.675,30.525 45.725,29.475 56.45,29.475 56.825,29.1 56.825,26.65 57.475,26 65.675,26 66.575,26.9 66.575,27.725 ; U13.13@47.575,40.975 47.575,41.175 v1(48.3,41.9)
  Signal Layer 2 w0.219: v1(45.65,41.9) v1(48.3,41.9)
  Bottom Layer w0.1: v1(44.678,32.153) 44.675,32.157 44.675,32.825 46.825,34.975 46.825,41.175 46.1,41.9 v1(45.65,41.9)
ETH1_MDINT: R104.1 U14.L4 | length 27.4
  Top Layer w0.09: U14.L4@69.475,35.65 v2@69.475,36.075
  Top Layer w0.1: v1(44.975,33.825) 45.225,34.075 45.225,34.5 R104.1@45.5,34.5
  Signal Layer 2 w0.219: v1(44.975,33.825) 46.75,35.6 57.425,35.6 57.5,35.525 58.475,35.525 58.675,35.725 64.475,35.725 64.975,35.225 65.175,35.225 66.55,35.225 67.025,35.7 68.9,35.7 v2(69.4,36.2)
ETH1_MDIO: R80.1 U13.12 U14.Y4 | length 51.4
  Top Layer w0.075: 68.3,27.725 68.525,27.95 68.525,28.561 69.721,29.757 69.721,30.779 69.498,31.002 69.498,31.127 U14.Y4@69.475,31.15
  Top Layer w0.1: U13.12@48.275,40.275 48.525,40.275 49.25,41 v1(49.25,43.375) 51.475,43.375 R80.1@51.525,43.425 ; v1(54.1,23.825) 55.525,23.825 56.45,24.75 64.4,24.75 65.05,24.1 66.15,24.1 66.8,24.75 67.166,24.75 67.75,25.334 67.75,27.5 67.931,27.681 68.256,27.681 68.3,27.725
  Bottom Layer w0.1: v1(49.25,43.375) 49.25,40.825 48.45,40.025 48.45,26.925 49.125,26.25 50.683,26.25 53.108,23.825 v1(54.1,23.825)
ETH1_NRST: R69.1 R73.1 R77.1 U5.26 | length 57.8
  Top Layer w0.1: R77.1@46.275,43.625 46.35,43.7 R73.1@46.35,44.575 R69.1@46.35,45.65 46.35,47.625 47.4,48.675 v1(47.4,49.975) ; v1(69.15,74.25) 69.15,75.35 69.275,75.475 U5.26@69.275,78.525
  Signal Layer 2 w0.1: v1(48.775,75) 48.897,75 49.047,75.15 51.975,75.15 52.85,74.275 55.2,74.275 55.375,74.45 59.637,74.45 59.837,74.25 v1(69.15,74.25)
  Bottom Layer w0.1: v1(47.4,49.975) 47.4,51.6 48.325,52.525 48.325,65.75 48.85,66.275 48.85,74.925 v1(48.775,75)
ETH1_RX_CLK: R79.1 U14.AA3 | length 55.3
  Top Layer w0.075: 67.35,27.725 67.35,28.3 68.975,29.925 U14.AA3@68.975,30.65
  Top Layer w0.1: v1(48.3,44.275) 48.3,43.75 R79.1@48.425,43.625 ; v1(52.45,23.325) 52.45,24.425 52.575,24.55 55.675,24.55 56.3,25.175 65.576,25.175 65.601,25.15 67,25.15 67.35,25.5 67.35,26.069 67.35,27.725
  Bottom Layer w0.1: v1(48.3,44.275) 48.3,44.175 47.55,43.425 47.55,41.925 47.975,41.5 47.975,30.984 47.916,30.925 47.184,30.925 47.125,30.866 47.125,30.534 47.184,30.475 47.916,30.475 47.975,30.416 47.975,30.159 47.916,30.1 47.184,30.1 47.125,30.041 47.125,29.684 47.184,29.625 47.866,29.625 47.925,29.566 47.925,29.4 47.925,29.375 47.925,29.3 47.825,29.2 47.228,29.2 47.128,29.1 47.128,28.9 47.228,28.8 47.825,28.8 47.925,28.7 47.925,28.5 47.825,28.4 47.228,28.4 47.128,28.3 47.128,28.1 47.228,28 47.825,28 47.925,27.9 47.925,27.7 47.825,27.6 47.228,27.6 47.128,27.5 47.128,27.3 47.228,27.2 47.825,27.2 47.925,27.1 47.925,27 47.925,26.325 48.1,26.15 48.566,26.15 48.891,25.825 50.45,25.825 50.85,25.425 50.85,23.775 51.3,23.325 v1(52.45,23.325)
ETH1_RXD0: R98.1 U14.Y7 | length 64.7
  Top Layer w0.075: 69.9,27.725 69.9,28.263 71.221,29.584 71.221,30.775 70.996,31 70.996,31.129 U14.Y7@70.975,31.15
  Top Layer w0.1: R98.1@52.425,38.2 v1(53.075,38.2) ; v1(56.95,23.95) 57,23.9 64.25,23.9 64.45,23.7 66.425,23.7 67,24.275 68.511,24.275 68.586,24.35 68.883,24.35 69.9,25.367 69.9,27.725
  Bottom Layer w0.1: v1(53.075,38.2) 59.85,38.2 60,38.35 60,38.525 59.9,38.625 59.45,38.625 59.15,38.625 59.05,38.725 59.05,40.146 58.95,40.246 58.75,40.246 58.65,40.146 58.65,38.725 58.55,38.625 58.35,38.625 58.25,38.725 58.25,40.146 58.15,40.246 57.95,40.246 57.85,40.146 57.85,38.725 57.75,38.625 57.55,38.625 57.45,38.725 57.45,40.146 57.35,40.246 57.15,40.246 57.05,40.146 57.05,38.725 56.95,38.625 56.75,38.625 56.65,38.725 56.65,40.146 56.55,40.246 56.35,40.246 56.25,40.146 56.25,38.725 56.15,38.625 56.05,38.625 52.75,38.625 52.4,38.275 52.4,27.4 54.4,25.4 55.65,25.4 56.824,24.226 56.824,24.197 56.95,24.072 v1(56.95,23.95)
ETH1_RXD1: R109.1 U14.AA7 | length 61.4
  Top Layer w0.075: 69.7,27.725 69.7,28.302 70.975,29.577 70.975,29.816 U14.AA7@70.975,30.65
  Top Layer w0.1: R109.1@52.425,34.975 52.525,35.075 v1(53.1,35.075) ; v1(57.875,24.325) 64.45,24.325 64.875,23.9 66.275,23.9 66.925,24.55 68.8,24.55 69.7,25.45 69.7,27.725
  Bottom Layer w0.1: v1(53.1,35.075) 53.1,37.625 53.283,37.808 53.357,37.808 53.375,37.825 53.591,37.825 53.65,37.766 53.65,37.625 53.725,37.55 57.3,37.55 57.4,37.45 57.4,37.25 57.3,37.15 53.75,37.15 53.65,37.05 53.65,36.85 53.75,36.75 57.3,36.75 57.4,36.65 57.4,36.45 57.3,36.35 53.75,36.35 53.65,36.25 53.65,36.05 53.75,35.95 57.3,35.95 57.4,35.85 57.4,35.65 57.3,35.55 53.75,35.55 53.65,35.45 53.65,35.15 53.65,34.95 52.625,33.925 52.625,27.475 54.2,25.9 56.325,25.9 57.875,24.35 v1(57.875,24.325)
ETH1_TX_EN: U13.16 U14.AA2 | length 67.3
  Top Layer w0.075: 66.8,27.725 66.8,28.45 68.475,30.125 U14.AA2@68.475,30.65
  Top Layer w0.1: v1(43.1,33.125) 43.1,32.25 44.175,31.175 44.175,30.6 45.5,29.275 53.25,29.275 53.35,29.175 53.675,29.175 53.975,29.175 54.075,29.075 54.075,28.35 54.175,28.25 54.375,28.25 54.475,28.35 54.475,29.075 54.575,29.175 54.775,29.175 54.875,29.075 54.875,28.35 54.975,28.25 55.175,28.25 55.275,28.35 55.275,29.075 55.375,29.175 55.575,29.175 55.675,29.075 55.675,28.35 55.775,28.25 55.975,28.25 56.075,28.35 56.075,29.075 56.175,29.175 56.275,29.175 56.55,28.9 56.55,26.525 57.3,25.775 57.425,25.775 57.575,25.775 57.875,25.775 57.975,25.675 57.975,25.5 58.075,25.4 58.275,25.4 58.375,25.5 58.375,25.675 58.475,25.775 58.675,25.775 58.775,25.675 58.775,25.5 58.875,25.4 59.075,25.4 59.175,25.5 59.175,25.675 59.275,25.775 59.475,25.775 59.575,25.675 59.575,25.5 59.675,25.4 59.875,25.4 59.975,25.5 59.975,25.675 60.075,25.775 60.275,25.775 60.375,25.675 60.375,25.5 60.475,25.4 60.675,25.4 60.775,25.5 60.775,25.675 60.875,25.775 61.075,25.775 61.175,25.675 61.175,25.5 61.275,25.4 61.475,25.4 61.575,25.5 61.575,25.675 61.675,25.775 61.875,25.775 61.975,25.675 61.975,25.5 62.075,25.4 62.275,25.4 62.375,25.5 62.375,25.675 62.475,25.775 62.675,25.775 62.775,25.675 62.775,25.5 62.875,25.4 63.075,25.4 63.175,25.5 63.175,25.675 63.275,25.775 63.475,25.775 63.575,25.675 63.575,25.5 63.675,25.4 63.875,25.4 63.975,25.5 63.975,25.675 64.075,25.775 64.275,25.775 64.375,25.675 64.375,25.5 64.475,25.4 64.675,25.4 64.775,25.5 64.775,25.675 64.875,25.775 65.075,25.775 65.175,25.675 65.175,25.5 65.275,25.4 65.475,25.4 65.575,25.5 65.575,25.675 65.675,25.775 65.775,25.775 65.775,25.8 66.8,26.825 66.8,27.725 ; v1(44.075,44.125) 44.375,44.125 44.475,44.125 44.575,44.225 44.575,47.425 44.675,47.525 44.875,47.525 44.975,47.425 44.975,44.225 45.075,44.125 45.375,44.125 45.4,44.125 45.55,44.125 45.7,43.975 45.7,42.475 46.075,42.1 U13.16@46.075,40.975
  Bottom Layer w0.1: v1(43.1,33.125) 43.1,34.549 44.67,36.119 44.67,43.53 v1(44.075,44.125)
ETH1_TXD0: U13.17 U14.AA9 | length 61.1
  Top Layer w0.075: 71.25,27.725 71.97,28.445 71.97,28.735 71.975,28.74 U14.AA9@71.975,30.65
  Top Layer w0.1: v1(39.7,35.725) 40.225,36.25 40.225,41.825 40.925,42.525 44.3,42.525 45.575,41.25 U13.17@45.575,40.975 ; v1(50.55,20.6) 53.1,20.6 53.2,20.7 55.375,20.7 58.175,23.5 66.45,23.5 66.925,23.025 67.827,23.025 68.752,23.95 69.049,23.95 70.32,25.221 70.32,26.795 71.25,27.725
  Bottom Layer w0.1: v1(39.7,35.725) 40.55,35.725 40.714,35.561 40.714,34.661 41.625,33.75 41.625,30.35 42.23,29.745 49.15,22.825 49.15,22.808 50.55,21.408 v1(50.55,20.6)
ETH1_TXD1: U13.18 U14.Y10 | length 62.4
  Top Layer w0.075: 72.099,27.725 72.644,28.27 72.644,30.337 72.721,30.414 72.721,30.779 72.498,31.002 72.498,31.127 U14.Y10@72.475,31.15
  Top Layer w0.1: v1(40.275,35.25) 40.3,35.225 40.5,35.425 40.5,41.7 41.05,42.25 44.05,42.25 45.075,41.225 U13.18@45.075,40.975 ; v1(49.875,20.075) 52.95,20.075 53.325,20.45 55.408,20.45 58.258,23.3 66.367,23.3 67.342,22.325 68.725,22.325 69.4,23 69.4,23.453 70.92,24.973 70.92,26.546 72.099,27.725
  Bottom Layer w0.1: v1(40.275,35.25) 40.275,34.725 41.425,33.575 41.425,30.25 49.875,21.8 v1(49.875,20.075)
ETH2_CLK: R50.1 U14.H5 | length 53
  Top Layer w0.09: U14.H5@69.975,37.15 70.1,37.275 v2(70.4,37.275)
  Top Layer w0.1: v1(46.375,49.15) 46.375,50.975 46.375,51.075 46.275,51.175 45.5,51.175 45.4,51.275 45.4,51.475 45.5,51.575 46.375,51.575 47.186,51.575 47.286,51.675 47.286,51.875 47.186,51.975 46.375,51.975 45.5,51.975 45.4,52.075 45.4,52.275 45.5,52.375 46.375,52.375 47.186,52.375 47.286,52.475 47.286,52.675 47.186,52.775 46.375,52.775 45.5,52.775 45.4,52.875 45.4,53.075 45.5,53.175 46.375,53.175 47.186,53.175 47.286,53.275 47.286,53.475 47.186,53.575 46.375,53.575 45.5,53.575 45.4,53.675 45.4,53.875 45.5,53.975 46.375,53.975 47.186,53.975 47.286,54.075 47.286,54.275 47.186,54.375 46.475,54.375 46.375,54.475 46.375,54.775 46.375,54.8 R50.1@46.375,56.85
  Bottom Layer w0.1: v1(46.375,49.15) 46.425,49.1 51.025,49.1 54.075,46.05 55.075,46.05 55.25,46.225 57,46.225 60.525,42.7 60.951,42.7 61.201,42.45 66.975,42.45 68.275,41.15 68.275,38.2 69.2,37.275 v2(70.4,37.275)
ETH2_CRS_DV: R36.1 U14.F4 | length 46.1
  Top Layer w0.09: v2(69.425,38.65) 69.463,38.613 69.463,38.163 U14.F4@69.475,38.15
  Top Layer w0.1: R36.1@52.425,63.65 v1(53.15,63.65) ; v1(61.1,61) 61.05,60.95 61.05,52.825 62.65,51.225 62.65,47.45 63.2,46.9 63.2,45.775 v1(63.125,45.7)
  Bottom Layer w0.1: v1(53.15,63.65) 53.68,63.65 56.228,61.102 56.33,61 56.82,61 56.92,60.9 56.92,60.258 57.02,60.158 57.22,60.158 57.32,60.258 57.32,61.052 57.42,61.152 57.62,61.152 57.72,61.052 57.72,60.258 57.82,60.158 58.02,60.158 58.12,60.258 58.12,61.052 58.22,61.152 58.42,61.152 58.52,61.052 58.52,60.258 58.62,60.158 58.82,60.158 58.92,60.258 58.92,61.052 59.02,61.152 59.22,61.152 59.32,61.052 59.32,60.258 59.42,60.158 59.62,60.158 59.72,60.258 59.72,61.052 59.82,61.152 60.02,61.152 60.12,61.052 60.12,60.258 60.22,60.158 60.42,60.158 60.52,60.258 60.52,60.9 60.62,61 60.895,61 v1(61.1,61) ; v1(63.125,45.7) 64.175,44.65 66.675,44.65 67.6,43.725 67.6,43 68.95,41.65 68.95,39.125 v2(69.425,38.65)
ETH2_MDC: U7.13 U14.G3 | length 47.4
  Top Layer w0.09: U14.G3@68.975,37.65 v2(69.4,37.65)
  Top Layer w0.1: U7.13@47.575,63.35 48.475,63.35 v1(49.1,63.975) ; v1@59.875,64.425 59.875,52.444 61.45,50.869 61.45,43.925 v1(61.775,43.6)
  Signal Layer 2 w0.219: v1(49.1,63.975) 49.425,64.3 v1(59.875,64.3)
  Bottom Layer w0.09: 67.3,43.125 67.3,42.725 68.575,41.45 68.575,38.475 v2(69.4,37.65)
  Bottom Layer w0.1: v1(61.775,43.6) 62.227,44.052 66.829,44.052 67.3,43.581 67.3,43.125
ETH2_MDINT: R30.1 U14.H4 | length 48.8
  Top Layer w0.09: v2(69.4,36.7) 69.4,37.075 U14.H4@69.475,37.15
  Top Layer w0.1: R30.1@48.425,66 v1(48.425,67.2) ; v1(55.4,67.2) 55.525,67.075 55.525,51.35 56.25,50.625 v1(56.25,45.575)
  Signal Layer 2 w0.219: v1(48.425,67.2) 48.45,67.175 55.375,67.175 v1(55.4,67.2)
  Bottom Layer w0.09: 65.175,39.975 66.975,39.975 67.875,39.075 67.875,37.825 69,36.7 v2(69.4,36.7)
  Bottom Layer w0.1: v1(56.25,45.575) 56.25,44.625 60.9,39.975 65.175,39.975
ETH2_MDIO: R31.1 U7.12 U14.J3 | length 48.6
  Top Layer w0.075: 65.175,37.975 66.212,36.938 67.559,36.938 67.601,36.897 68.728,36.897 U14.J3@68.975,36.65
  Top Layer w0.1: U7.12@48.275,62.65 48.975,62.65 49.725,63.4 49.725,65.075 v1(50.45,65.8) R31.1@51.525,65.8 ; v1(55.05,65.8) 55.275,65.575 55.275,44.325 60.65,38.95 64.2,38.95 65.175,37.975
  Signal Layer 2 w0.219: v1(50.45,65.8) v1(55.05,65.8)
